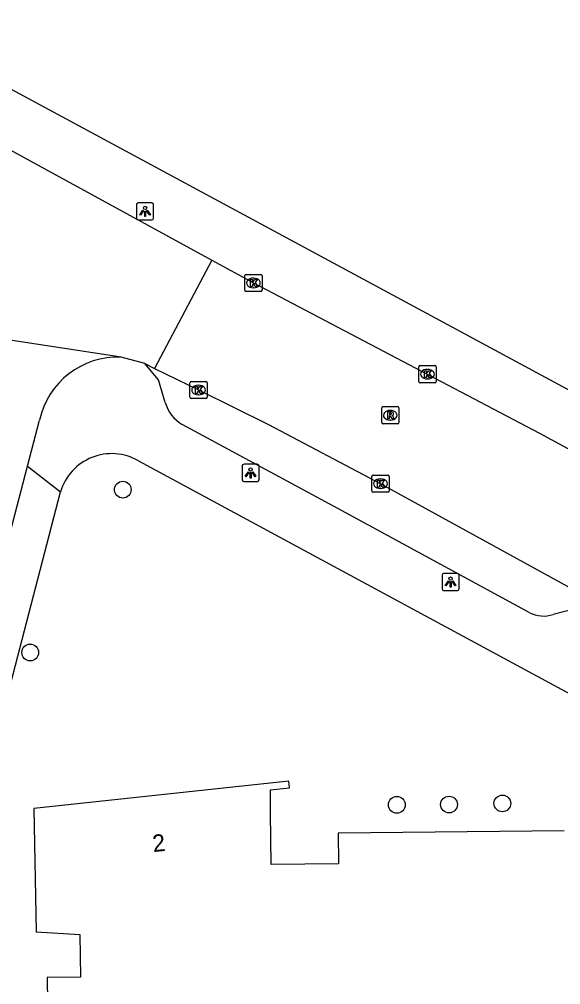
# Model space of a CAD drawing. Extents: x 161258 to 161838, y 380836 to 381727.
# Drawn here: x 161624.3 to 161655.9, y 381041 to 381097.3 of the extents above; entities that cross this region are included whole.
import ezdxf

# ---------------------------------------------------------------- set-up
doc = ezdxf.new("R2010")
doc.units = 0
for name, color, linetype in [('IMGEO_Boom', 7, 'Continuous'), ('IMGEO_Fietspad_gesloten', 7, 'Continuous'), ('IMGEO_Kolk', 7, 'Continuous'), ('IMGEO_Lichtpunt', 7, 'Continuous'), ('IMGEO_Pand', 7, 'Continuous'), ('IMGEO_Pand_nummerreeks', 7, 'Continuous'), ('IMGEO_Rijbaan_lokaal_open', 7, 'Continuous'), ('IMGEO_Rioolput', 7, 'Continuous'), ('IMGEO_Voetpad_open', 7, 'Continuous')]:
    doc.layers.add(name, color=color, linetype=linetype)

msp = doc.modelspace()

# ---------------------------------------------------------------- linework, layer by layer
at = {"layer": 'IMGEO_Boom'}
for centre in [(161630.384, 381069.91), (161624.985, 381060.41), (161646.377, 381051.519), (161649.42, 381051.535), (161652.532, 381051.604)]:
    msp.add_circle(centre, 0.489, dxfattribs=at)
at = {"layer": 'IMGEO_Fietspad_gesloten'}
for points in [[(161624.834, 381071.281), (161625.531, 381073.954)], [(161614.41, 381031.306), (161624.834, 381071.281)]]:
    msp.add_lwpolyline(points, dxfattribs=at)
msp.add_arc((161630.103, 381072.97), 4.676, 87.79, 167.8547, dxfattribs=at)
at = {"layer": 'IMGEO_Kolk'}
for p, q in [((161637.508, 381081.541), (161637.508, 381082.393)), ((161637.583, 381082.467), (161638.435, 381082.467)), ((161638.509, 381082.393), (161638.509, 381081.541)), ((161637.996, 381082.247), (161638.021, 381082.247)), ((161638.435, 381081.467), (161637.583, 381081.467)), ((161638.019, 381081.687), (161637.994, 381081.687)), ((161647.664, 381076.221), (161647.664, 381077.073)), ((161647.739, 381077.147), (161648.591, 381077.147)), ((161648.152, 381076.927), (161648.177, 381076.927)), ((161648.665, 381077.073), (161648.665, 381076.221)), ((161634.306, 381075.296), (161634.306, 381076.148)), ((161634.381, 381076.222), (161635.233, 381076.222)), ((161635.307, 381076.148), (161635.307, 381075.296)), ((161648.591, 381076.147), (161647.739, 381076.147)), ((161648.175, 381076.367), (161648.15, 381076.367)), ((161634.794, 381076.002), (161634.819, 381076.002)), ((161635.233, 381075.222), (161634.381, 381075.222)), ((161634.817, 381075.442), (161634.792, 381075.442)), ((161644.922, 381069.832), (161644.922, 381070.684)), ((161644.997, 381070.758), (161645.849, 381070.758)), ((161645.41, 381070.538), (161645.435, 381070.538)), ((161645.923, 381070.684), (161645.923, 381069.832)), ((161645.433, 381069.978), (161645.408, 381069.978)), ((161645.849, 381069.758), (161644.997, 381069.758))]:
    msp.add_line(p, q, dxfattribs=at)
for points in [[(161637.508, 381081.541), (161637.508, 381082.393)], [(161637.583, 381082.467), (161638.435, 381082.467)], [(161638.509, 381082.393), (161638.509, 381081.541)], [(161637.829, 381082.167), (161637.952, 381082.167), (161637.952, 381082.016), (161638.082, 381082.167), (161638.246, 381082.167), (161638.1, 381082.016), (161638.253, 381081.767), (161638.101, 381081.767), (161638.016, 381081.931), (161637.952, 381081.864), (161637.952, 381081.767), (161637.829, 381081.767), (161637.829, 381082.167)], [(161638.435, 381081.467), (161637.583, 381081.467)], [(161647.664, 381076.221), (161647.664, 381077.073)], [(161647.739, 381077.147), (161648.591, 381077.147)], [(161647.985, 381076.847), (161648.108, 381076.847), (161648.108, 381076.696), (161648.238, 381076.847), (161648.402, 381076.847), (161648.256, 381076.696), (161648.409, 381076.447), (161648.257, 381076.447), (161648.172, 381076.611), (161648.108, 381076.544), (161648.108, 381076.447), (161647.985, 381076.447), (161647.985, 381076.847)], [(161648.665, 381077.073), (161648.665, 381076.221)], [(161634.306, 381075.296), (161634.306, 381076.148)], [(161634.381, 381076.222), (161635.233, 381076.222)], [(161635.307, 381076.148), (161635.307, 381075.296)], [(161648.591, 381076.147), (161647.739, 381076.147)], [(161634.627, 381075.922), (161634.75, 381075.922), (161634.75, 381075.771), (161634.88, 381075.922), (161635.044, 381075.922), (161634.898, 381075.771), (161635.051, 381075.522), (161634.899, 381075.522), (161634.814, 381075.686), (161634.75, 381075.619), (161634.75, 381075.522), (161634.627, 381075.522), (161634.627, 381075.922)], [(161635.233, 381075.222), (161634.381, 381075.222)], [(161644.922, 381069.832), (161644.922, 381070.684)], [(161644.997, 381070.758), (161645.849, 381070.758)], [(161645.243, 381070.458), (161645.366, 381070.458), (161645.366, 381070.307), (161645.496, 381070.458), (161645.66, 381070.458), (161645.514, 381070.307), (161645.667, 381070.058), (161645.515, 381070.058), (161645.43, 381070.222), (161645.366, 381070.155), (161645.366, 381070.058), (161645.243, 381070.058), (161645.243, 381070.458)], [(161645.923, 381070.684), (161645.923, 381069.832)], [(161645.849, 381069.758), (161644.997, 381069.758)]]:
    msp.add_lwpolyline(points, dxfattribs=at)
for centre, start, end in [((161637.585, 381082.391), 91.552, 178.448), ((161637.585, 381082.391), 91.552, 178.448), ((161638.433, 381082.391), 1.552, 88.448), ((161638.433, 381082.391), 1.552, 88.448), ((161637.585, 381081.543), 181.552, 268.448), ((161637.585, 381081.543), 181.552, 268.448), ((161638.433, 381081.543), 271.552, 358.448), ((161638.433, 381081.543), 271.552, 358.448), ((161647.741, 381077.071), 91.552, 178.448), ((161647.741, 381077.071), 91.552, 178.448), ((161648.589, 381077.071), 1.552, 88.448), ((161648.589, 381077.071), 1.552, 88.448), ((161634.383, 381076.146), 91.552, 178.448), ((161634.383, 381076.146), 91.552, 178.448), ((161635.231, 381076.146), 1.552, 88.448), ((161635.231, 381076.146), 1.552, 88.448), ((161647.741, 381076.223), 181.552, 268.448), ((161647.741, 381076.223), 181.552, 268.448), ((161648.589, 381076.223), 271.552, 358.448), ((161648.589, 381076.223), 271.552, 358.448), ((161634.383, 381075.298), 181.552, 268.448), ((161634.383, 381075.298), 181.552, 268.448), ((161635.231, 381075.298), 271.552, 358.448), ((161635.231, 381075.298), 271.552, 358.448), ((161644.999, 381070.682), 91.552, 178.448), ((161644.999, 381070.682), 91.552, 178.448), ((161645.847, 381070.682), 1.552, 88.448), ((161645.847, 381070.682), 1.552, 88.448), ((161644.999, 381069.834), 181.552, 268.448), ((161644.999, 381069.834), 181.552, 268.448), ((161645.847, 381069.834), 271.552, 358.448), ((161645.847, 381069.834), 271.552, 358.448)]:
    msp.add_arc(centre, 0.0765, start, end, dxfattribs=at)
for centre, major_axis, ratio, start_param, end_param in [((161637.995, 381081.967), (-0.387, 0.002), 0.722429, 4.712389, 7.853982), ((161638.02, 381081.967), (-0.39, 0.002), 0.717154, 1.570796, 4.712389), ((161648.151, 381076.647), (-0.387, 0.002), 0.722429, 4.712389, 7.853982), ((161648.176, 381076.647), (-0.39, 0.002), 0.717154, 1.570796, 4.712389), ((161634.793, 381075.722), (-0.387, 0.002), 0.722429, 4.712389, 7.853982), ((161634.818, 381075.722), (-0.39, 0.002), 0.717154, 1.570796, 4.712389), ((161645.409, 381070.258), (-0.387, 0.002), 0.722429, 4.712389, 7.853982), ((161645.434, 381070.258), (-0.39, 0.002), 0.717154, 1.570796, 4.712389)]:
    msp.add_ellipse(centre, major_axis=major_axis, ratio=ratio, start_param=start_param, end_param=end_param, dxfattribs=at)
at = {"layer": 'IMGEO_Lichtpunt'}
for p, q in [((161631.186, 381086.546), (161631.186, 381085.739)), ((161631.186, 381086.546), (161631.186, 381085.739)), ((161632.088, 381086.641), (161631.28, 381086.641)), ((161632.088, 381086.641), (161631.28, 381086.641)), ((161632.182, 381085.739), (161632.182, 381086.546)), ((161632.182, 381085.739), (161632.182, 381086.546)), ((161631.28, 381085.645), (161632.088, 381085.645)), ((161631.28, 381085.645), (161632.088, 381085.645)), ((161637.344, 381071.291), (161637.344, 381070.484)), ((161637.344, 381071.291), (161637.344, 381070.484)), ((161638.246, 381071.386), (161637.438, 381071.386)), ((161638.246, 381071.386), (161637.438, 381071.386)), ((161638.34, 381070.484), (161638.34, 381071.291)), ((161638.34, 381070.484), (161638.34, 381071.291)), ((161637.438, 381070.39), (161638.246, 381070.39)), ((161637.438, 381070.39), (161638.246, 381070.39)), ((161649.013, 381064.924), (161649.013, 381064.117)), ((161649.013, 381064.924), (161649.013, 381064.117)), ((161649.915, 381065.019), (161649.107, 381065.019)), ((161649.915, 381065.019), (161649.107, 381065.019)), ((161650.009, 381064.117), (161650.009, 381064.924)), ((161650.009, 381064.117), (161650.009, 381064.924)), ((161649.107, 381064.023), (161649.915, 381064.023)), ((161649.107, 381064.023), (161649.915, 381064.023))]:
    msp.add_line(p, q, dxfattribs=at)
for points in [[(161631.56, 381086.21), (161631.599, 381086.182), (161631.411, 381085.92), (161631.373, 381085.947), (161631.56, 381086.21)], [(161631.662, 381086.162), (161631.709, 381086.162), (161631.709, 381085.84), (161631.662, 381085.84), (161631.662, 381086.162)], [(161631.772, 381086.182), (161631.81, 381086.209), (161631.997, 381085.947), (161631.958, 381085.919), (161631.772, 381086.182)], [(161637.718, 381070.955), (161637.757, 381070.927), (161637.569, 381070.665), (161637.531, 381070.692), (161637.718, 381070.955)], [(161637.82, 381070.907), (161637.867, 381070.907), (161637.867, 381070.585), (161637.82, 381070.585), (161637.82, 381070.907)], [(161637.93, 381070.927), (161637.968, 381070.954), (161638.155, 381070.692), (161638.116, 381070.664), (161637.93, 381070.927)], [(161649.387, 381064.588), (161649.426, 381064.56), (161649.238, 381064.298), (161649.2, 381064.325), (161649.387, 381064.588)], [(161649.489, 381064.54), (161649.536, 381064.54), (161649.536, 381064.218), (161649.489, 381064.218), (161649.489, 381064.54)], [(161649.599, 381064.56), (161649.637, 381064.587), (161649.824, 381064.325), (161649.785, 381064.297), (161649.599, 381064.56)]]:
    msp.add_lwpolyline(points, dxfattribs=at)
for centre in [(161631.685, 381086.344), (161637.843, 381071.089), (161649.512, 381064.722)]:
    msp.add_circle(centre, 0.0994, dxfattribs=at)
for centre, start, end in [((161631.28, 381086.546), 90, 180), ((161631.28, 381086.546), 90, 180), ((161632.088, 381086.546), 0, 90), ((161632.088, 381086.546), 0, 90), ((161631.28, 381085.739), 180, 270), ((161631.28, 381085.739), 180, 270), ((161632.088, 381085.739), 270, 0), ((161632.088, 381085.739), 270, 360), ((161637.438, 381071.291), 90, 180), ((161637.438, 381071.291), 90, 180), ((161638.246, 381071.291), 0, 90), ((161638.246, 381071.291), 0, 90), ((161637.438, 381070.484), 180, 270), ((161637.438, 381070.484), 180, 270), ((161638.246, 381070.484), 270, 0), ((161638.246, 381070.484), 270, 360), ((161649.107, 381064.924), 90, 180), ((161649.107, 381064.924), 90, 180), ((161649.915, 381064.924), 0, 90), ((161649.915, 381064.924), 0, 90), ((161649.107, 381064.117), 180, 270), ((161649.107, 381064.117), 180, 270), ((161649.915, 381064.117), 270, 0), ((161649.915, 381064.117), 270, 360)]:
    msp.add_arc(centre, 0.0946, start, end, dxfattribs=at)
at = {"layer": 'IMGEO_Pand'}
for points in [[(161639.011, 381051.044), (161639, 381052.39), (161640.116, 381052.521), (161640.074, 381052.905), (161625.192, 381051.313), (161625.335, 381044.112), (161627.879, 381043.946), (161627.912, 381041.469), (161625.982, 381041.445), (161626.113, 381030.848), (161633.254, 381030.942), (161633.22, 381033.1), (161632.37, 381033.087), (161632.354, 381034.635), (161643.217, 381034.788), (161643.261, 381032.174), (161642.947, 381032.074), (161643.044, 381031.769), (161649.92, 381033.973), (161662.306, 381037.947)], [(161656.14, 381049.999), (161642.958, 381049.862), (161642.977, 381048.072), (161639.037, 381048.03), (161639.011, 381051.044)]]:
    msp.add_lwpolyline(points, dxfattribs=at)
at = {"layer": 'IMGEO_Rijbaan_lokaal_open'}
for points in [[(161611.018, 381096.621), (161623.338, 381089.989), (161635.58, 381083.294)], [(161635.58, 381083.294), (161632.244, 381076.986)], [(161635.58, 381083.294), (161638.009, 381081.966), (161651.628, 381074.813), (161654.689, 381073.206), (161664.516, 381067.867), (161669.88, 381065.045), (161677.177, 381060.856), (161680.698, 381058.941), (161685.459, 381056.689)], [(161630.283, 381077.643), (161623.675, 381078.64)], [(161631.678, 381077.263), (161630.283, 381077.643)], [(161631.678, 381077.263), (161632.244, 381076.986)], [(161632.244, 381076.986), (161634.807, 381075.723), (161638.895, 381073.701), (161645.436, 381070.252), (161658.944, 381062.836)]]:
    msp.add_lwpolyline(points, dxfattribs=at)
at = {"layer": 'IMGEO_Rioolput'}
for p, q in [((161645.493, 381073.825), (161645.493, 381074.677)), ((161645.568, 381074.751), (161646.42, 381074.751)), ((161645.981, 381074.531), (161646.006, 381074.531)), ((161646.494, 381074.677), (161646.494, 381073.825)), ((161646.004, 381073.971), (161645.979, 381073.971)), ((161646.42, 381073.751), (161645.568, 381073.751))]:
    msp.add_line(p, q, dxfattribs=at)
for points in [[(161645.493, 381073.825), (161645.493, 381074.677)], [(161645.568, 381074.751), (161646.42, 381074.751)], [(161646.082, 381074.449), (161645.83, 381074.451), (161645.83, 381074.051)], [(161646.494, 381074.677), (161646.494, 381073.825)], [(161645.83, 381074.051), (161645.954, 381074.051), (161645.954, 381074.213), (161645.965, 381074.213)], [(161646.008, 381074.37), (161645.954, 381074.37), (161645.954, 381074.289)], [(161645.954, 381074.289), (161646.006, 381074.289)], [(161646.012, 381074.184), (161646.083, 381074.051), (161646.223, 381074.051), (161646.158, 381074.177)], [(161646.42, 381073.751), (161645.568, 381073.751)]]:
    msp.add_lwpolyline(points, dxfattribs=at)
for centre, radius, start, end in [((161645.57, 381074.675), 0.0765, 91.552, 178.448), ((161645.57, 381074.675), 0.0765, 91.552, 178.448), ((161646.081, 381074.339), 0.109, 350.3612, 89.416), ((161646.418, 381074.675), 0.0765, 1.552, 88.448), ((161646.418, 381074.675), 0.0765, 1.552, 88.448), ((161645.964, 381074.16), 0.0533, 26.0293, 88.6989), ((161645.99, 381074.478), 0.19, 274.7715, 282.9687), ((161646.014, 381074.274), 0.0964, 77.0061, 93.1865), ((161646.028, 381074.331), 0.0378, 276.6634, 79.6772), ((161646.079, 381074.339), 0.112, 277.5842, 350.9817), ((161646.063, 381074.124), 0.108, 29.5134, 73.7905), ((161645.57, 381073.827), 0.0765, 181.552, 268.448), ((161645.57, 381073.827), 0.0765, 181.552, 268.448), ((161646.418, 381073.827), 0.0765, 271.552, 358.448), ((161646.418, 381073.827), 0.0765, 271.552, 358.448)]:
    msp.add_arc(centre, radius, start, end, dxfattribs=at)
for centre, major_axis, ratio, start_param, end_param in [((161645.98, 381074.251), (-0.387, 0.002), 0.722429, 4.712389, 7.853982), ((161646.005, 381074.251), (-0.39, 0.002), 0.717154, 1.570796, 4.712389)]:
    msp.add_ellipse(centre, major_axis=major_axis, ratio=ratio, start_param=start_param, end_param=end_param, dxfattribs=at)
at = {"layer": 'IMGEO_Voetpad_open'}
for points in [[(161686.794, 381059.495), (161683.729, 381060.833), (161676.825, 381064.703), (161608.252, 381101.703), (161603.367, 381104.463), (161599.292, 381107.15)], [(161632.865, 381074.999), (161632.464, 381076.312), (161631.678, 381077.263)], [(161654.103, 381062.734), (161642.932, 381068.81), (161633.849, 381073.709)], [(161631.294, 381071.59), (161662.556, 381054.709), (161664.588, 381056.855), (161675.471, 381050.931)], [(161624.834, 381071.281), (161626.757, 381069.781)], [(161616.62, 381030.824), (161626.757, 381069.781)], [(161656.781, 381062.954), (161655.5, 381062.629)]]:
    msp.add_lwpolyline(points, dxfattribs=at)
for centre, radius, start, end in [((161634.97, 381075.584), 2.185, 195.5374, 239.1347), ((161629.736, 381068.903), 3.106, 59.8996, 163.5768), ((161654.927, 381064.348), 1.812, 242.9563, 288.447)]:
    msp.add_arc(centre, radius, start, end, dxfattribs=at)

# ---------------------------------------------------------------- texts
at = {"layer": 'IMGEO_Pand_nummerreeks'}
msp.add_text('2', height=1, rotation=6.1062, dxfattribs=at).set_placement((161632.168, 381048.761))

doc.saveas('drawing.dxf')
